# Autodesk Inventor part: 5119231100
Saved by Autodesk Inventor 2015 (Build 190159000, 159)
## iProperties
Created: 2020-07
Part Number: 5119231100
Checked By: TraceParts S.A.
Material: Generic
Catalog Web Link: www.traceparts.com
Document SubType Name: Modeling
Designer: TraceParts
Density: 1 g/cm^3
Appearance: Default
Company: TraceParts S.A.
Author: TraceParts
REFERENCE: 5119231100
DESIGN: HIT-1250 P 1,5KW (230/400V 50HZ) - 5119231100
SUPPLIER: Soler & Palau
TraceParts.PartNumber: 10-20122018-119595
TraceParts.PartTitle: HIB-P/HIT-P
TraceParts.InstanceId: 10-20122018-119595CGFPX3JBJHA81BRDK99R1WOQQ
TraceParts.PartStatus: Published
TraceParts.PartVersion: 1.0.2
TRACEPARTS: TRACEPARTS
TraceParts.PartLanguage: en
TraceParts.ClassPath: SOLER_PALAU:10-20122018-119595
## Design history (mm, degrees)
feature "5119231100"
body "Solid1"
